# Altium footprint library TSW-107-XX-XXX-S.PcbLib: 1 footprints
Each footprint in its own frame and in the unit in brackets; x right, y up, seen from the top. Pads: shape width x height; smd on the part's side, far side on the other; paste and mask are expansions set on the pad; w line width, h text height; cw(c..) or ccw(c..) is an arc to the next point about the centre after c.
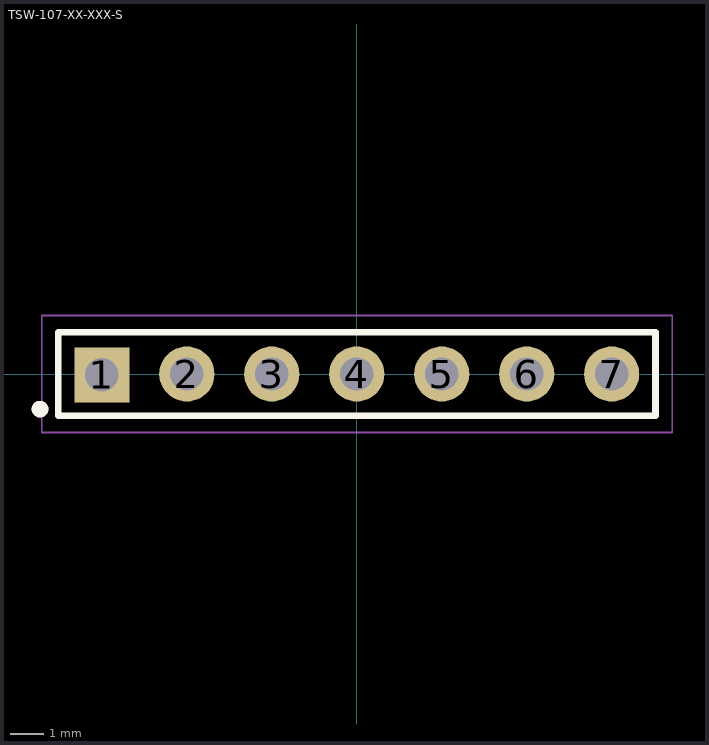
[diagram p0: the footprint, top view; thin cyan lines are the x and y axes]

## TSW-107-XX-XXX-S [mm] "2.54mm pitch, 7 pin, terminal strip; straight, single row"
height 2.54
pads (7):
  rect 1.65x1.65 hole 1 mask+0: 1(-7.62,-0.025)
  round 1.65 hole 1 mask+0: 2(-5.08,0) 3(-2.54,0) 4(0,0) 5(2.54,0) 6(5.08,0) 7(7.62,0)
Top Overlay:
  circle w0.25: c-9.47,-1.05 r0.125
  lines w0.2: -8.92,-1.25 -8.92,1.25 8.93,1.25 8.93,-1.25 -8.92,-1.25
Mechanical 12:
  lines w0.001: -8.92,-1.25 -8.92,1.25 8.93,1.25 8.93,-1.25 -8.92,-1.25
Mechanical 13:
  circle w0.25: c-9.47,-1.05 r0.125
  lines w0.1: -8.92,-1.25 -8.92,1.25 8.93,1.25 8.93,-1.25 -8.92,-1.25
  text ".Designator" at 0,0 h1.52
Mechanical 15:
  lines w0.05: -9.42,-1.75 -9.42,1.75 9.43,1.75 9.43,-1.75 -9.42,-1.75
